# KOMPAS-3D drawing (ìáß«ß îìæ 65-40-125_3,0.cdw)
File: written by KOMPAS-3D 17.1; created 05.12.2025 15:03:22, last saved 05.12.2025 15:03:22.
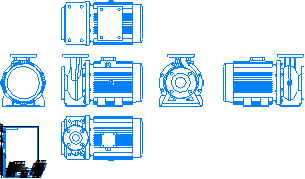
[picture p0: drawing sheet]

Sheet 1: A4, portrait

Title block, sheet 1: name: Насос МНС / 65-40-125_3,0; material: Сталь 10  ГОСТ 1050-88; mass: 119,59; sheets: 1; sheet format: A4

Views: Проекционный вид 2, Проекционный вид 3, Проекционный вид 4, Проекционный вид 5, Проекционный вид 6
Referenced files in \\adlc.lan\data\АДЛ_ПКД\3D-модели\ADL production\Насосы ГРАНПАМП\Насосы ГРАНПАМП серии МНС\KOMPAS 3D\: Насос МНС 65-40-125_3,0.m3d
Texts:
  Andrey
  АДЛ
Dimensions and other numbers on the sheet: 1:1; 1; 65-40-125_3,0; 119,59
